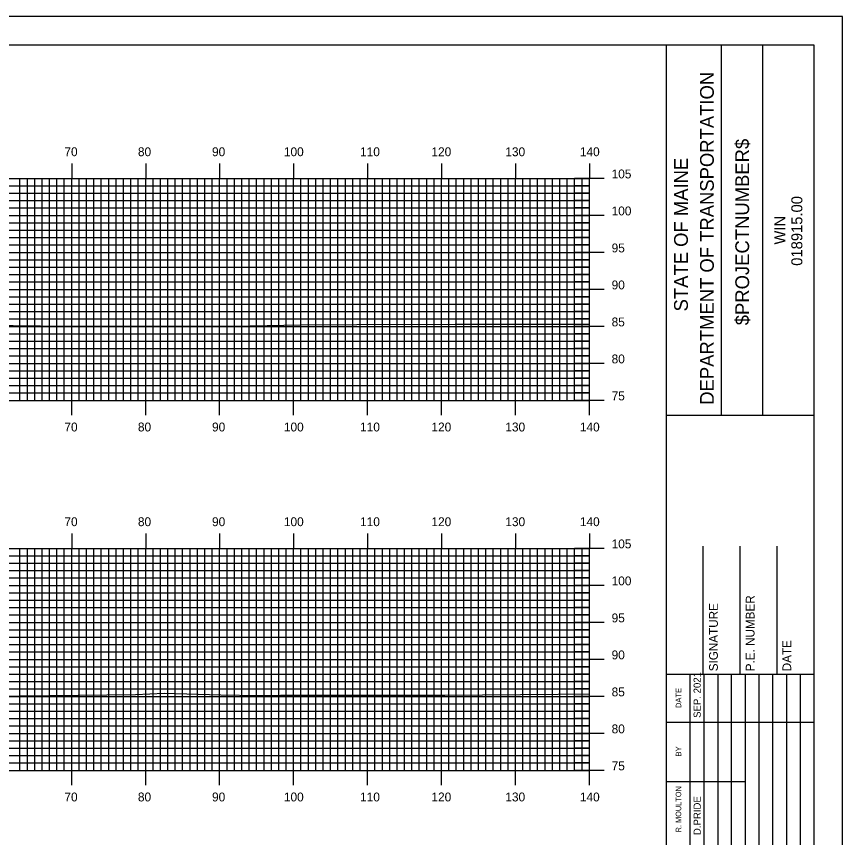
# Model space of a CAD drawing. Extents: x 1757856 to 1758199, y 442591 to 442811.
# Drawn here: x 1758084.2 to 1758195.8, y 442699.6 to 442810.5 of the extents above; entities that cross this region are included whole.
import ezdxf

# ---------------------------------------------------------------- set-up
doc = ezdxf.new("R2010")
doc.units = 0
for name, color, linetype in [('BORDER', 7, 'Continuous'), ('H_V ANNOTATION', 7, 'Continuous'), ('MAJOR', 7, 'Continuous'), ('MINOR', 7, 'Continuous'), ('PLOT BOUNDARY', 7, 'Continuous'), ('S_Roadway_Centerline', 7, 'Continuous')]:
    doc.layers.add(name, color=color, linetype=linetype)

msp = doc.modelspace()

# ---------------------------------------------------------------- linework, layer by layer
at = {"layer": 'BORDER'}
for p, q in [((1758172.02, 442596.67), (1758172.02, 442806.67)), ((1758179.48, 442756.66), (1758179.48, 442806.66)), ((1758185.07, 442756.66), (1758185.07, 442806.66)), ((1758172.02, 442756.65), (1758192.02, 442756.65)), ((1758177.02, 442721.67), (1758177.02, 442738.97)), ((1758182.02, 442721.67), (1758182.02, 442738.97)), ((1758187.02, 442721.67), (1758187.02, 442738.97)), ((1758172.02, 442721.67), (1758192.02, 442721.67))]:
    msp.add_line(p, q, dxfattribs=at)
msp.add_lwpolyline([(1757872.02, 442596.67), (1758192.02, 442596.67), (1758192.02, 442806.67), (1757872.02, 442806.67)], close=True, dxfattribs=at)
for points in [[(1758175.25, 442715.17), (1758175.25, 442721.67)], [(1758177.12, 442686.68), (1758177.12, 442721.67)], [(1758178.98, 442721.67), (1758178.98, 442686.68)], [(1758180.84, 442686.68), (1758180.84, 442721.67)], [(1758182.71, 442686.68), (1758182.71, 442721.67)], [(1758184.57, 442686.68), (1758184.57, 442721.67)], [(1758186.43, 442686.68), (1758186.43, 442721.67)], [(1758188.3, 442686.68), (1758188.3, 442721.67)], [(1758190.16, 442686.68), (1758190.16, 442721.67)], [(1758175.25, 442686.68), (1758175.25, 442720.26)], [(1758172.02, 442715.17), (1758192.02, 442715.17)], [(1758172.02, 442707.17), (1758175.25, 442707.17)], [(1758175.25, 442707.17), (1758182.71, 442707.17)]]:
    msp.add_lwpolyline(points, dxfattribs=at)
at = {"layer": 'MAJOR'}
for p, q in [((1758091.62, 442790.67), (1758091.62, 442788.67)), ((1758101.62, 442790.67), (1758101.62, 442788.67)), ((1758111.62, 442790.67), (1758111.62, 442788.67)), ((1758121.62, 442790.67), (1758121.62, 442788.67)), ((1758131.62, 442790.67), (1758131.62, 442788.67)), ((1758141.62, 442790.67), (1758141.62, 442788.67)), ((1758151.62, 442790.67), (1758151.62, 442788.67)), ((1758161.62, 442790.67), (1758161.62, 442788.67)), ((1757881.62, 442788.67), (1758161.62, 442788.67)), ((1757881.62, 442788.67), (1758161.62, 442788.67)), ((1758091.62, 442758.67), (1758091.62, 442788.67)), ((1758101.62, 442758.67), (1758101.62, 442788.67)), ((1758111.62, 442758.67), (1758111.62, 442788.67)), ((1758121.62, 442758.67), (1758121.62, 442788.67)), ((1758131.62, 442758.67), (1758131.62, 442788.67)), ((1758141.62, 442758.67), (1758141.62, 442788.67)), ((1758151.62, 442758.67), (1758151.62, 442788.67)), ((1758163.63, 442788.67), (1758159.62, 442788.67)), ((1758161.62, 442758.67), (1758161.62, 442788.67)), ((1758161.62, 442758.67), (1758161.62, 442788.67)), ((1757881.62, 442783.67), (1758161.62, 442783.67)), ((1758163.63, 442783.67), (1758159.62, 442783.67)), ((1757881.62, 442778.67), (1758161.62, 442778.67)), ((1758163.63, 442778.67), (1758159.62, 442778.67)), ((1757881.62, 442773.67), (1758161.62, 442773.67)), ((1758163.63, 442773.67), (1758159.62, 442773.67)), ((1757881.62, 442768.67), (1758161.62, 442768.67)), ((1758163.63, 442768.67), (1758159.62, 442768.67)), ((1757881.62, 442763.67), (1758161.62, 442763.67)), ((1758163.63, 442763.67), (1758159.62, 442763.67)), ((1757881.62, 442758.67), (1758161.62, 442758.67)), ((1757881.62, 442758.67), (1758161.62, 442758.67)), ((1758091.62, 442756.66), (1758091.62, 442758.67)), ((1758101.62, 442756.66), (1758101.62, 442758.67)), ((1758111.62, 442756.66), (1758111.62, 442758.67)), ((1758121.62, 442756.66), (1758121.62, 442758.67)), ((1758131.62, 442756.66), (1758131.62, 442758.67)), ((1758141.62, 442756.66), (1758141.62, 442758.67)), ((1758151.62, 442756.66), (1758151.62, 442758.67)), ((1758163.63, 442758.67), (1758159.62, 442758.67)), ((1758161.62, 442756.66), (1758161.62, 442758.67)), ((1758091.62, 442740.67), (1758091.62, 442738.67)), ((1758101.62, 442740.67), (1758101.62, 442738.67)), ((1758111.62, 442740.67), (1758111.62, 442738.67)), ((1758121.62, 442740.67), (1758121.62, 442738.67)), ((1758131.62, 442740.67), (1758131.62, 442738.67)), ((1758141.62, 442740.67), (1758141.62, 442738.67)), ((1758151.62, 442740.67), (1758151.62, 442738.67)), ((1758161.62, 442740.67), (1758161.62, 442738.67)), ((1757881.62, 442738.67), (1758161.62, 442738.67)), ((1757881.62, 442738.67), (1758161.62, 442738.67)), ((1758091.62, 442708.67), (1758091.62, 442738.67)), ((1758101.62, 442708.67), (1758101.62, 442738.67)), ((1758111.62, 442708.67), (1758111.62, 442738.67)), ((1758121.62, 442708.67), (1758121.62, 442738.67)), ((1758131.62, 442708.67), (1758131.62, 442738.67)), ((1758141.62, 442708.67), (1758141.62, 442738.67)), ((1758151.62, 442708.67), (1758151.62, 442738.67)), ((1758163.63, 442738.67), (1758159.62, 442738.67)), ((1758161.62, 442708.67), (1758161.62, 442738.67)), ((1758161.62, 442708.67), (1758161.62, 442738.67)), ((1757881.62, 442733.67), (1758161.62, 442733.67)), ((1758163.63, 442733.67), (1758159.62, 442733.67)), ((1757881.62, 442728.67), (1758161.62, 442728.67)), ((1758163.63, 442728.67), (1758159.62, 442728.67)), ((1757881.62, 442723.67), (1758161.62, 442723.67)), ((1758163.63, 442723.67), (1758159.62, 442723.67)), ((1757881.62, 442718.67), (1758161.62, 442718.67)), ((1758163.63, 442718.67), (1758159.62, 442718.67)), ((1757881.62, 442713.67), (1758161.62, 442713.67)), ((1758163.63, 442713.67), (1758159.62, 442713.67)), ((1757881.62, 442708.67), (1758161.62, 442708.67)), ((1757881.62, 442708.67), (1758161.62, 442708.67)), ((1758091.62, 442706.66), (1758091.62, 442708.67)), ((1758101.62, 442706.66), (1758101.62, 442708.67)), ((1758111.62, 442706.66), (1758111.62, 442708.67)), ((1758121.62, 442706.66), (1758121.62, 442708.67)), ((1758131.62, 442706.66), (1758131.62, 442708.67)), ((1758141.62, 442706.66), (1758141.62, 442708.67)), ((1758151.62, 442706.66), (1758151.62, 442708.67)), ((1758163.63, 442708.67), (1758159.62, 442708.67)), ((1758161.62, 442706.66), (1758161.62, 442708.67))]:
    msp.add_line(p, q, dxfattribs=at)
at = {"layer": 'MINOR'}
for p, q in [((1758084.62, 442758.67), (1758084.62, 442788.67)), ((1758085.62, 442758.67), (1758085.62, 442788.67)), ((1758086.62, 442758.67), (1758086.62, 442788.67)), ((1758087.62, 442758.67), (1758087.62, 442788.67)), ((1758088.62, 442758.67), (1758088.62, 442788.67)), ((1758089.62, 442758.67), (1758089.62, 442788.67)), ((1758090.62, 442758.67), (1758090.62, 442788.67)), ((1758092.62, 442758.67), (1758092.62, 442788.67)), ((1758093.62, 442758.67), (1758093.62, 442788.67)), ((1758094.62, 442758.67), (1758094.62, 442788.67)), ((1758095.62, 442758.67), (1758095.62, 442788.67)), ((1758096.62, 442758.67), (1758096.62, 442788.67)), ((1758097.62, 442758.67), (1758097.62, 442788.67)), ((1758098.62, 442758.67), (1758098.62, 442788.67)), ((1758099.62, 442758.67), (1758099.62, 442788.67)), ((1758100.62, 442758.67), (1758100.62, 442788.67)), ((1758102.62, 442758.67), (1758102.62, 442788.67)), ((1758103.62, 442758.67), (1758103.62, 442788.67)), ((1758104.62, 442758.67), (1758104.62, 442788.67)), ((1758105.62, 442758.67), (1758105.62, 442788.67)), ((1758106.62, 442758.67), (1758106.62, 442788.67)), ((1758107.62, 442758.67), (1758107.62, 442788.67)), ((1758108.62, 442758.67), (1758108.62, 442788.67)), ((1758109.62, 442758.67), (1758109.62, 442788.67)), ((1758110.62, 442758.67), (1758110.62, 442788.67)), ((1758112.62, 442758.67), (1758112.62, 442788.67)), ((1758113.62, 442758.67), (1758113.62, 442788.67)), ((1758114.62, 442758.67), (1758114.62, 442788.67)), ((1758115.62, 442758.67), (1758115.62, 442788.67)), ((1758116.62, 442758.67), (1758116.62, 442788.67)), ((1758117.62, 442758.67), (1758117.62, 442788.67)), ((1758118.62, 442758.67), (1758118.62, 442788.67)), ((1758119.62, 442758.67), (1758119.62, 442788.67)), ((1758120.62, 442758.67), (1758120.62, 442788.67)), ((1758122.62, 442758.67), (1758122.62, 442788.67)), ((1758123.62, 442758.67), (1758123.62, 442788.67)), ((1758124.62, 442758.67), (1758124.62, 442788.67)), ((1758125.62, 442758.67), (1758125.62, 442788.67)), ((1758126.62, 442758.67), (1758126.62, 442788.67)), ((1758127.62, 442758.67), (1758127.62, 442788.67)), ((1758128.62, 442758.67), (1758128.62, 442788.67)), ((1758129.62, 442758.67), (1758129.62, 442788.67)), ((1758130.62, 442758.67), (1758130.62, 442788.67)), ((1758132.62, 442758.67), (1758132.62, 442788.67)), ((1758133.62, 442758.67), (1758133.62, 442788.67)), ((1758134.62, 442758.67), (1758134.62, 442788.67)), ((1758135.62, 442758.67), (1758135.62, 442788.67)), ((1758136.62, 442758.67), (1758136.62, 442788.67)), ((1758137.62, 442758.67), (1758137.62, 442788.67)), ((1758138.62, 442758.67), (1758138.62, 442788.67)), ((1758139.62, 442758.67), (1758139.62, 442788.67)), ((1758140.62, 442758.67), (1758140.62, 442788.67)), ((1758142.62, 442758.67), (1758142.62, 442788.67)), ((1758143.62, 442758.67), (1758143.62, 442788.67)), ((1758144.62, 442758.67), (1758144.62, 442788.67)), ((1758145.62, 442758.67), (1758145.62, 442788.67)), ((1758146.62, 442758.67), (1758146.62, 442788.67)), ((1758147.62, 442758.67), (1758147.62, 442788.67)), ((1758148.62, 442758.67), (1758148.62, 442788.67)), ((1758149.62, 442758.67), (1758149.62, 442788.67)), ((1758150.62, 442758.67), (1758150.62, 442788.67)), ((1758152.62, 442758.67), (1758152.62, 442788.67)), ((1758153.62, 442758.67), (1758153.62, 442788.67)), ((1758154.62, 442758.67), (1758154.62, 442788.67)), ((1758155.62, 442758.67), (1758155.62, 442788.67)), ((1758156.62, 442758.67), (1758156.62, 442788.67)), ((1758157.62, 442758.67), (1758157.62, 442788.67)), ((1758158.62, 442758.67), (1758158.62, 442788.67)), ((1758159.62, 442758.67), (1758159.62, 442788.67)), ((1758160.62, 442758.67), (1758160.62, 442788.67)), ((1757881.62, 442787.67), (1758161.62, 442787.67)), ((1758161.62, 442787.67), (1758159.62, 442787.67)), ((1757881.62, 442786.67), (1758161.62, 442786.67)), ((1758161.62, 442786.67), (1758159.62, 442786.67)), ((1757881.62, 442785.67), (1758161.62, 442785.67)), ((1758161.62, 442785.67), (1758159.62, 442785.67)), ((1757881.62, 442784.67), (1758161.62, 442784.67)), ((1758161.62, 442784.67), (1758159.62, 442784.67)), ((1757881.62, 442782.67), (1758161.62, 442782.67)), ((1757881.62, 442781.67), (1758161.62, 442781.67)), ((1758161.62, 442782.67), (1758159.62, 442782.67)), ((1758161.62, 442781.67), (1758159.62, 442781.67)), ((1757881.62, 442780.67), (1758161.62, 442780.67)), ((1758161.62, 442780.67), (1758159.62, 442780.67)), ((1757881.62, 442779.67), (1758161.62, 442779.67)), ((1758161.62, 442779.67), (1758159.62, 442779.67)), ((1757881.62, 442777.67), (1758161.62, 442777.67)), ((1758161.62, 442777.67), (1758159.62, 442777.67)), ((1757881.62, 442776.67), (1758161.62, 442776.67)), ((1758161.62, 442776.67), (1758159.62, 442776.67)), ((1757881.62, 442775.67), (1758161.62, 442775.67)), ((1758161.62, 442775.67), (1758159.62, 442775.67)), ((1757881.62, 442774.67), (1758161.62, 442774.67)), ((1758161.62, 442774.67), (1758159.62, 442774.67)), ((1757881.62, 442772.67), (1758161.62, 442772.67)), ((1758161.62, 442772.67), (1758159.62, 442772.67)), ((1757881.62, 442771.67), (1758161.62, 442771.67)), ((1758161.62, 442771.67), (1758159.62, 442771.67)), ((1757881.62, 442770.67), (1758161.62, 442770.67)), ((1758161.62, 442770.67), (1758159.62, 442770.67)), ((1757881.62, 442769.67), (1758161.62, 442769.67)), ((1758161.62, 442769.67), (1758159.62, 442769.67)), ((1757881.62, 442767.67), (1758161.62, 442767.67)), ((1758161.62, 442767.67), (1758159.62, 442767.67)), ((1757881.62, 442766.67), (1758161.62, 442766.67)), ((1758161.62, 442766.67), (1758159.62, 442766.67)), ((1757881.62, 442765.67), (1758161.62, 442765.67)), ((1758161.62, 442765.67), (1758159.62, 442765.67)), ((1757881.62, 442764.67), (1758161.62, 442764.67)), ((1758161.62, 442764.67), (1758159.62, 442764.67)), ((1757881.62, 442762.67), (1758161.62, 442762.67)), ((1758161.62, 442762.67), (1758159.62, 442762.67)), ((1757881.62, 442761.67), (1758161.62, 442761.67)), ((1758161.62, 442761.67), (1758159.62, 442761.67)), ((1757881.62, 442760.67), (1758161.62, 442760.67)), ((1758161.62, 442760.67), (1758159.62, 442760.67)), ((1757881.62, 442759.67), (1758161.62, 442759.67)), ((1758161.62, 442759.67), (1758159.62, 442759.67)), ((1758084.62, 442708.67), (1758084.62, 442738.67)), ((1758085.62, 442708.67), (1758085.62, 442738.67)), ((1758086.62, 442708.67), (1758086.62, 442738.67)), ((1758087.62, 442708.67), (1758087.62, 442738.67)), ((1758088.62, 442708.67), (1758088.62, 442738.67)), ((1758089.62, 442708.67), (1758089.62, 442738.67)), ((1758090.62, 442708.67), (1758090.62, 442738.67)), ((1758092.62, 442708.67), (1758092.62, 442738.67)), ((1758093.62, 442708.67), (1758093.62, 442738.67)), ((1758094.62, 442708.67), (1758094.62, 442738.67)), ((1758095.62, 442708.67), (1758095.62, 442738.67)), ((1758096.62, 442708.67), (1758096.62, 442738.67)), ((1758097.62, 442708.67), (1758097.62, 442738.67)), ((1758098.62, 442708.67), (1758098.62, 442738.67)), ((1758099.62, 442708.67), (1758099.62, 442738.67)), ((1758100.62, 442708.67), (1758100.62, 442738.67)), ((1758102.62, 442708.67), (1758102.62, 442738.67)), ((1758103.62, 442708.67), (1758103.62, 442738.67)), ((1758104.62, 442708.67), (1758104.62, 442738.67)), ((1758105.62, 442708.67), (1758105.62, 442738.67)), ((1758106.62, 442708.67), (1758106.62, 442738.67)), ((1758107.62, 442708.67), (1758107.62, 442738.67)), ((1758108.62, 442708.67), (1758108.62, 442738.67)), ((1758109.62, 442708.67), (1758109.62, 442738.67)), ((1758110.62, 442708.67), (1758110.62, 442738.67)), ((1758112.62, 442708.67), (1758112.62, 442738.67)), ((1758113.62, 442708.67), (1758113.62, 442738.67)), ((1758114.62, 442708.67), (1758114.62, 442738.67)), ((1758115.62, 442708.67), (1758115.62, 442738.67)), ((1758116.62, 442708.67), (1758116.62, 442738.67)), ((1758117.62, 442708.67), (1758117.62, 442738.67)), ((1758118.62, 442708.67), (1758118.62, 442738.67)), ((1758119.62, 442708.67), (1758119.62, 442738.67)), ((1758120.62, 442708.67), (1758120.62, 442738.67)), ((1758122.62, 442708.67), (1758122.62, 442738.67)), ((1758123.62, 442708.67), (1758123.62, 442738.67)), ((1758124.62, 442708.67), (1758124.62, 442738.67)), ((1758125.62, 442708.67), (1758125.62, 442738.67)), ((1758126.62, 442708.67), (1758126.62, 442738.67)), ((1758127.62, 442708.67), (1758127.62, 442738.67)), ((1758128.62, 442708.67), (1758128.62, 442738.67)), ((1758129.62, 442708.67), (1758129.62, 442738.67)), ((1758130.62, 442708.67), (1758130.62, 442738.67)), ((1758132.62, 442708.67), (1758132.62, 442738.67)), ((1758133.62, 442708.67), (1758133.62, 442738.67)), ((1758134.62, 442708.67), (1758134.62, 442738.67)), ((1758135.62, 442708.67), (1758135.62, 442738.67)), ((1758136.62, 442708.67), (1758136.62, 442738.67)), ((1758137.62, 442708.67), (1758137.62, 442738.67)), ((1758138.62, 442708.67), (1758138.62, 442738.67)), ((1758139.62, 442708.67), (1758139.62, 442738.67)), ((1758140.62, 442708.67), (1758140.62, 442738.67)), ((1758142.62, 442708.67), (1758142.62, 442738.67)), ((1758143.62, 442708.67), (1758143.62, 442738.67)), ((1758144.62, 442708.67), (1758144.62, 442738.67)), ((1758145.62, 442708.67), (1758145.62, 442738.67)), ((1758146.62, 442708.67), (1758146.62, 442738.67)), ((1758147.62, 442708.67), (1758147.62, 442738.67)), ((1758148.62, 442708.67), (1758148.62, 442738.67)), ((1758149.62, 442708.67), (1758149.62, 442738.67)), ((1758150.62, 442708.67), (1758150.62, 442738.67)), ((1758152.62, 442708.67), (1758152.62, 442738.67)), ((1758153.62, 442708.67), (1758153.62, 442738.67)), ((1758154.62, 442708.67), (1758154.62, 442738.67)), ((1758155.62, 442708.67), (1758155.62, 442738.67)), ((1758156.62, 442708.67), (1758156.62, 442738.67)), ((1758157.62, 442708.67), (1758157.62, 442738.67)), ((1758158.62, 442708.67), (1758158.62, 442738.67)), ((1758159.62, 442708.67), (1758159.62, 442738.67)), ((1758160.62, 442708.67), (1758160.62, 442738.67)), ((1757881.62, 442737.67), (1758161.62, 442737.67)), ((1758161.62, 442737.67), (1758159.62, 442737.67)), ((1757881.62, 442736.67), (1758161.62, 442736.67)), ((1758161.62, 442736.67), (1758159.62, 442736.67)), ((1757881.62, 442735.67), (1758161.62, 442735.67)), ((1758161.62, 442735.67), (1758159.62, 442735.67)), ((1757881.62, 442734.67), (1758161.62, 442734.67)), ((1758161.62, 442734.67), (1758159.62, 442734.67)), ((1757881.62, 442732.67), (1758161.62, 442732.67)), ((1758161.62, 442732.67), (1758159.62, 442732.67)), ((1757881.62, 442731.67), (1758161.62, 442731.67)), ((1758161.62, 442731.67), (1758159.62, 442731.67)), ((1757881.62, 442730.67), (1758161.62, 442730.67)), ((1758161.62, 442730.67), (1758159.62, 442730.67)), ((1757881.62, 442729.67), (1758161.62, 442729.67)), ((1758161.62, 442729.67), (1758159.62, 442729.67)), ((1757881.62, 442727.67), (1758161.62, 442727.67)), ((1758161.62, 442727.67), (1758159.62, 442727.67)), ((1757881.62, 442726.67), (1758161.62, 442726.67)), ((1758161.62, 442726.67), (1758159.62, 442726.67)), ((1757881.62, 442725.67), (1758161.62, 442725.67)), ((1757881.62, 442724.67), (1758161.62, 442724.67)), ((1758161.62, 442725.67), (1758159.62, 442725.67)), ((1758161.62, 442724.67), (1758159.62, 442724.67)), ((1757881.62, 442722.67), (1758161.62, 442722.67)), ((1758161.62, 442722.67), (1758159.62, 442722.67)), ((1757881.62, 442721.67), (1758161.62, 442721.67)), ((1758161.62, 442721.67), (1758159.62, 442721.67)), ((1757881.62, 442720.67), (1758161.62, 442720.67)), ((1758161.62, 442720.67), (1758159.62, 442720.67)), ((1757881.62, 442719.67), (1758161.62, 442719.67)), ((1758161.62, 442719.67), (1758159.62, 442719.67)), ((1757881.62, 442717.67), (1758161.62, 442717.67)), ((1758161.62, 442717.67), (1758159.62, 442717.67)), ((1757881.62, 442716.67), (1758161.62, 442716.67)), ((1758161.62, 442716.67), (1758159.62, 442716.67)), ((1757881.62, 442715.67), (1758161.62, 442715.67)), ((1757881.62, 442714.67), (1758161.62, 442714.67)), ((1758161.62, 442715.67), (1758159.62, 442715.67)), ((1758161.62, 442714.67), (1758159.62, 442714.67)), ((1757881.62, 442712.67), (1758161.62, 442712.67)), ((1758161.62, 442712.67), (1758159.62, 442712.67)), ((1757881.62, 442711.67), (1758161.62, 442711.67)), ((1758161.62, 442711.67), (1758159.62, 442711.67)), ((1757881.62, 442710.67), (1758161.62, 442710.67)), ((1758161.62, 442710.67), (1758159.62, 442710.67)), ((1757881.62, 442709.67), (1758161.62, 442709.67)), ((1758161.62, 442709.67), (1758159.62, 442709.67))]:
    msp.add_line(p, q, dxfattribs=at)
at = {"layer": 'PLOT BOUNDARY'}
msp.add_lwpolyline([(1757855.84, 442590.55), (1758195.84, 442590.55), (1758195.84, 442810.55), (1757855.84, 442810.55)], close=True, dxfattribs=at)
at = {"layer": 'S_Roadway_Centerline'}
for points in [[(1758072.67, 442768.91), (1758091.05, 442768.72), (1758091.36, 442768.71), (1758091.56, 442768.72), (1758092.34, 442768.72), (1758111.01, 442768.69), (1758115.73, 442768.74), (1758122.58, 442768.86), (1758130.19, 442768.92), (1758143.48, 442768.96), (1758149.76, 442768.97), (1758153.44, 442768.97), (1758161.62, 442768.98)], [(1758080.79, 442718.7), (1758100.24, 442718.9), (1758104.14, 442719.08), (1758111.77, 442718.88), (1758116.88, 442718.78), (1758119.85, 442718.82), (1758132.53, 442718.82), (1758138.37, 442718.82), (1758139.81, 442718.85), (1758142.08, 442718.85), (1758157.38, 442718.95), (1758161.62, 442719.03)]]:
    msp.add_lwpolyline(points, dxfattribs=at)

# ---------------------------------------------------------------- texts
at = {"layer": 'BORDER'}
for s, height, p in [('DEPARTMENT OF TRANSPORTATION', 1.8635, (1758178.44, 442758.08)), ('$PROJECTNUMBER$', 1.8635, (1758183.21, 442768.82)), ('STATE OF MAINE', 1.8635, (1758174.93, 442770.69)), ('018915.00', 1.491, (1758190.41, 442776.86)), ('WIN', 1.491, (1758188.1, 442779.73)), ('P.E. NUMBER', 1.1811, (1758183.94, 442722.06)), ('SIGNATURE', 1.181, (1758178.98, 442722.06)), ('DATE', 1.181, (1758188.9, 442722.06)), ('SEP. 2021', 0.969, (1758176.67, 442715.76)), ('DATE', 0.743, (1758174.03, 442717.08)), ('BY', 0.743, (1758174.03, 442710.54)), ('R. MOULTON', 0.745, (1758174.03, 442700.28)), ('D.PRIDE', 0.969, (1758176.67, 442699.92))]:
    msp.add_text(s, height=height, rotation=90, dxfattribs=at).set_placement(p)
at = {"layer": 'H_V ANNOTATION'}
for s, p in [('70', (1758090.63, 442791.67)), ('80', (1758100.57, 442791.67)), ('90', (1758110.59, 442791.67)), ('100', (1758120.31, 442791.67)), ('110', (1758130.61, 442791.67)), ('120', (1758140.26, 442791.67)), ('130', (1758150.25, 442791.67)), ('140', (1758160.33, 442791.67)), ('105', (1758164.62, 442788.67)), ('100', (1758164.62, 442783.67)), ('95', (1758164.62, 442778.67)), ('90', (1758164.62, 442773.67)), ('85', (1758164.62, 442768.67)), ('80', (1758164.62, 442763.67)), ('75', (1758164.62, 442758.67)), ('70', (1758090.63, 442754.47)), ('80', (1758100.57, 442754.47)), ('90', (1758110.59, 442754.47)), ('100', (1758120.31, 442754.47)), ('110', (1758130.61, 442754.47)), ('120', (1758140.26, 442754.47)), ('130', (1758150.25, 442754.47)), ('140', (1758160.33, 442754.47)), ('70', (1758090.63, 442741.67)), ('80', (1758100.57, 442741.67)), ('90', (1758110.59, 442741.67)), ('100', (1758120.31, 442741.67)), ('110', (1758130.61, 442741.67)), ('120', (1758140.26, 442741.67)), ('130', (1758150.25, 442741.67)), ('140', (1758160.33, 442741.67)), ('105', (1758164.62, 442738.67)), ('100', (1758164.62, 442733.67)), ('95', (1758164.62, 442728.67)), ('90', (1758164.62, 442723.67)), ('85', (1758164.62, 442718.67)), ('80', (1758164.62, 442713.67)), ('75', (1758164.62, 442708.67)), ('70', (1758090.63, 442704.47)), ('80', (1758100.57, 442704.47)), ('90', (1758110.59, 442704.47)), ('100', (1758120.31, 442704.47)), ('110', (1758130.61, 442704.47)), ('120', (1758140.26, 442704.47)), ('130', (1758150.25, 442704.47)), ('140', (1758160.33, 442704.47))]:
    msp.add_text(s, height=1.2, dxfattribs=at).set_placement(p)

doc.saveas('drawing.dxf')
